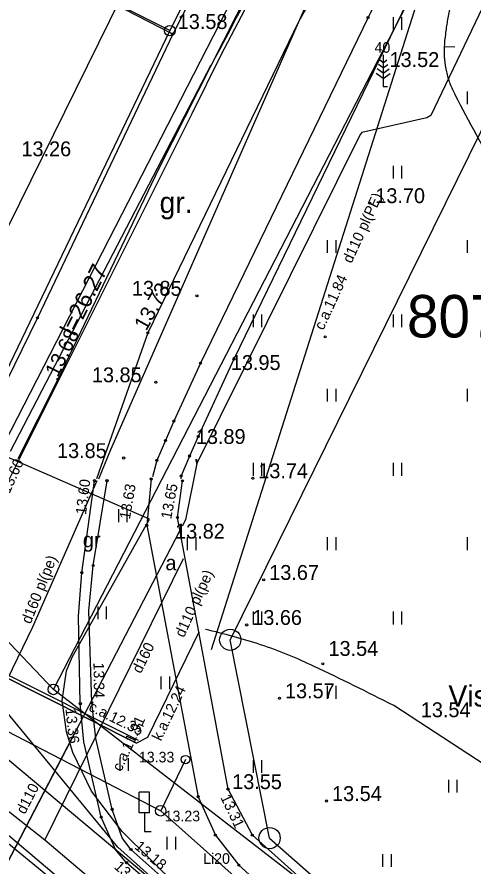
# Model space of a CAD drawing. Extents: x 503877 to 504025, y 304562 to 304725.
# Drawn here: x 503931.43 to 503952.92, y 304618.66 to 304658.69 of the extents above; entities that cross this region are included whole.
import ezdxf

# ---------------------------------------------------------------- set-up
doc = ezdxf.new("R2010")
doc.units = 0
for name, color, linetype in [('10', 7, 'Continuous'), ('13', 7, 'Continuous'), ('24', 7, 'Continuous'), ('25', 7, 'Continuous'), ('APGS_ACRL_####_####_#', 7, 'Continuous'), ('APGS_ELEM_####_####_#', 7, 'Continuous'), ('APGS_VADP_ZSPR_####_#', 7, 'Continuous'), ('APGS_VADP_ZSPR_TKST_#', 7, 'Continuous'), ('BUVE_EKAS_ADRS_TKST_#', 7, 'Continuous'), ('CELI_CMAL_####_####_#', 7, 'Continuous'), ('CELI_CSEG_####_TKST_#', 7, 'Continuous'), ('CELI_ELEM_####_####_#', 7, 'Continuous'), ('CELI_TAKA_####_####_#', 7, 'Continuous'), ('ELEK_ACRL_####_####_#', 7, 'Continuous'), ('ELEK_ELEM_####_####_#', 7, 'Continuous'), ('ELEK_STUT_####_####_#', 7, 'Continuous'), ('ELEK_VADP_VSPR_####_#', 7, 'Continuous'), ('ELEK_VADP_VSPR_TKST_#', 7, 'Continuous'), ('ELEK_VADV_ZSPR_####_#', 7, 'Continuous'), ('GAZE_VADP_VSP1_####_#', 7, 'Continuous'), ('GAZE_VADP_VSP2_####_#', 7, 'Continuous'), ('GAZE_VADP_ZSPD_TKST_#', 7, 'Continuous'), ('Level 37', 7, 'Continuous'), ('Level 46', 7, 'Continuous'), ('NORB_ZOGS_ZSTP_####_#', 7, 'Continuous'), ('RELJ_AATZ_####_TKST_#', 7, 'Continuous'), ('RELJ_ELEM_####_####_#', 7, 'Continuous'), ('RELJ_HORZ_KRIT_####_#', 7, 'Continuous'), ('RELJ_HORZ_PAMT_####_#', 7, 'Continuous'), ('SAKK_KKAN_####_####_#', 7, 'Continuous'), ('SAKK_KKAN_####_TKST_#', 7, 'Continuous'), ('SAKT_VADP_KABE_####_#', 7, 'Continuous'), ('SAKT_VADP_NEDR_####_#', 7, 'Continuous'), ('SKAN_VADP_PAST_####_I', 7, 'Continuous'), ('SKAN_VADP_SPDK_TKST_I', 7, 'Continuous'), ('TERT_DIAM_####_TKST_#', 7, 'Continuous'), ('TERT_ELEM_####_####_#', 7, 'Continuous'), ('UDTK_VADP_UDEN_####_#', 7, 'Continuous'), ('UDTK_VADP_UDEN_TKST_#', 7, 'Continuous')]:
    doc.layers.add(name, color=color, linetype=linetype)

msp = doc.modelspace()

# ---------------------------------------------------------------- linework, layer by layer
at = {"layer": '10'}
for centre in [(503938.631, 304658.048), (503933.144, 304627.024)]:
    msp.add_circle(centre, 0.25, dxfattribs=at)
at = {"layer": '13'}
msp.add_line((503926.838, 304633.583), (503933.144, 304627.024), dxfattribs=at)
at = {"layer": '24'}
for p, q in [((503951.131, 304682.848), (503938.631, 304658.048)), ((503938.631, 304658.048), (503897.583, 304678.92)), ((503933.144, 304627.024), (503952.592, 304664.678)), ((503938.631, 304658.048), (503926.838, 304633.583)), ((503960.823, 304605.633), (503933.144, 304627.024))]:
    msp.add_line(p, q, dxfattribs=at)
at = {"layer": '25'}
msp.add_line((503924.947, 304625.297), (503985.325, 304574.255), dxfattribs=at)
at = {"layer": 'APGS_ACRL_####_####_#'}
msp.add_line((503930.237, 304617.463), (503934.246, 304625.165), dxfattribs=at)
at = {"layer": 'APGS_ELEM_####_####_#'}
for p, q in [((503939.903, 304637.829), (503939.84, 304637.828)), ((503939.853, 304637.828), (503939.853, 304637.789)), ((503939.874, 304637.829), (503939.874, 304637.789)), ((503939.904, 304637.662), (503939.904, 304637.85))]:
    msp.add_line(p, q, dxfattribs=at)
msp.add_circle((503939.904, 304637.662), 0.00907, dxfattribs=at)
msp.add_ellipse((503939.864, 304637.789), major_axis=(0, 0.0151), ratio=0.695971, start_param=1.570796, end_param=4.712389, dxfattribs=at)
at = {"layer": 'APGS_VADP_ZSPR_####_#'}
msp.add_line((503939.108, 304634.506), (503930.237, 304617.463), dxfattribs=at)
for points in [[(503962.091, 304677.36), (503950.94, 304654.055), (503950.749, 304653.94), (503947.69, 304653.253), (503947.598, 304653.154), (503939.904, 304637.662)], [(503939.904, 304637.662), (503939.373, 304635.015), (503939.215, 304634.711)]]:
    msp.add_lwpolyline(points, dxfattribs=at)
at = {"layer": 'CELI_CMAL_####_####_#'}
for p, q in [((503937.753, 304636.934), (503937.542, 304634.751)), ((503934.483, 304632.519), (503935.08, 304636.853)), ((503938.994, 304635.119), (503939.23, 304636.849)), ((503941.374, 304622.324), (503938.994, 304635.119)), ((503937.542, 304634.751), (503939.968, 304621.969)), ((503934.319, 304630.471), (503934.483, 304632.519)), ((503934.411, 304626.352), (503934.319, 304630.471)), ((503934.578, 304624.555), (503934.411, 304626.352)), ((503935.397, 304621.008), (503934.578, 304624.555)), ((503942.522, 304620.157), (503941.374, 304622.324)), ((503939.968, 304621.969), (503940.779, 304620.16)), ((503936.063, 304619.479), (503935.397, 304621.008)), ((503940.779, 304620.16), (503941.882, 304618.748)), ((503950.55, 304613.018), (503942.522, 304620.157)), ((503936.593, 304618.863), (503936.063, 304619.479)), ((503946.502, 304610.359), (503936.593, 304618.863)), ((503941.882, 304618.748), (503948.456, 304612.839))]:
    msp.add_line(p, q, dxfattribs=at)
for points in [[(503964.434, 304683.858), (503952.135, 304666.661), (503951.57, 304665.843), (503951.057, 304664.963), (503950.617, 304664.103), (503947.974, 304658.67), (503940.075, 304642.39), (503938.82, 304639.661), (503938.43, 304638.742), (503938.02, 304637.811), (503937.81, 304637.042)], [(503960.285, 304675.777), (503953.257, 304665.972), (503952.709, 304665.141), (503952.2, 304664.263), (503951.73, 304663.364), (503949.548, 304658.848), (503941.655, 304642.576), (503939.971, 304638.935), (503939.558, 304638.014), (503939.163, 304637.077), (503939.144, 304636.942)]]:
    msp.add_lwpolyline(points, dxfattribs=at)
at = {"layer": 'CELI_ELEM_####_####_#'}
for p, q in [((503937.678, 304622.186), (503937.178, 304622.186)), ((503937.178, 304621.217), (503937.178, 304622.186)), ((503937.678, 304621.217), (503937.678, 304622.186)), ((503937.678, 304621.217), (503937.178, 304621.217)), ((503937.432, 304621.217), (503937.432, 304620.339)), ((503937.432, 304620.339), (503937.747, 304620.339))]:
    msp.add_line(p, q, dxfattribs=at)
at = {"layer": 'CELI_TAKA_####_####_#'}
for p, q in [((503935.016, 304632.859), (503935.67, 304636.852)), ((503934.812, 304630.718), (503935.016, 304632.859)), ((503934.952, 304626.401), (503934.812, 304630.718)), ((503935.148, 304624.712), (503934.952, 304626.401)), ((503935.915, 304621.375), (503935.148, 304624.712)), ((503936.38, 304620.026), (503935.915, 304621.375)), ((503936.798, 304619.482), (503936.38, 304620.026)), ((503946.769, 304610.685), (503936.798, 304619.482))]:
    msp.add_line(p, q, dxfattribs=at)
at = {"layer": 'ELEK_ACRL_####_####_#'}
for p, q in [((503923.292, 304631.393), (503937.063, 304624.493)), ((503937.153, 304624.623), (503923.308, 304631.521))]:
    msp.add_line(p, q, dxfattribs=at)
at = {"layer": 'ELEK_ELEM_####_####_#'}
for centre, radius in [((503939.367, 304623.718), 0.2), ((503938.2, 304621.309), 0.25)]:
    msp.add_circle(centre, radius, dxfattribs=at)
at = {"layer": 'ELEK_STUT_####_####_#'}
msp.add_line((503939.367, 304623.718), (503938.2, 304621.309), dxfattribs=at)
at = {"layer": 'ELEK_VADP_VSPR_####_#'}
for p, q in [((503937.063, 304624.493), (503923.292, 304631.393)), ((503939.998, 304629.719), (503937.58, 304624.758)), ((503937.58, 304624.758), (503937.063, 304624.493))]:
    msp.add_line(p, q, dxfattribs=at)
at = {"layer": 'ELEK_VADV_ZSPR_####_#'}
for p, q in [((503952.461, 304666.267), (503940.581, 304628.881)), ((503914.775, 304633.411), (503938.2, 304621.309)), ((503938.2, 304621.309), (503972.501, 304590.85))]:
    msp.add_line(p, q, dxfattribs=at)
at = {"layer": 'GAZE_VADP_VSP1_####_#'}
for p, q in [((503935.844, 304638.319), (503946.879, 304663.413)), ((503935.279, 304636.943), (503935.844, 304638.319))]:
    msp.add_line(p, q, dxfattribs=at)
at = {"layer": 'GAZE_VADP_VSP2_####_#'}
for p, q in [((503932.176, 304629.976), (503935.202, 304636.857)), ((503928.011, 304621.403), (503932.176, 304629.976))]:
    msp.add_line(p, q, dxfattribs=at)
at = {"layer": 'Level 37'}
for points in [[(503931.488, 304637.906), (503933.361, 304641.635), (503938.149, 304651.603), (503944.187, 304663.552), (503950.647, 304675.682), (503952.251, 304677.936)], [(503956.692, 304677.708), (503950.737, 304669.048), (503944.715, 304658.502), (503937.591, 304643.813), (503935.18, 304636.937)]]:
    msp.add_lwpolyline(points, dxfattribs=at)
at = {"layer": 'Level 46'}
for p, q in [((503926.16, 304638.991), (503960.977, 304709.6)), ((503980.064, 304707.607), (503941.479, 304629.359)), ((503943.333, 304620.019), (503941.479, 304629.359)), ((503943.333, 304620.019), (504006.701, 304564.361))]:
    msp.add_line(p, q, dxfattribs=at)
for centre in [(503941.479, 304629.359), (503943.333, 304620.019)]:
    msp.add_circle(centre, 0.5, dxfattribs=at)
at = {"layer": 'NORB_ZOGS_ZSTP_####_#'}
msp.add_line((503938.767, 304657.889), (503932.419, 304661.163), dxfattribs=at)
msp.add_lwpolyline([(503945.353, 304670.815), (503938.767, 304657.889), (503932.391, 304644.523), (503929.857, 304639.392)], dxfattribs=at)
at = {"layer": 'RELJ_ELEM_####_####_#'}
for centre in [(503947.974, 304658.67), (503938.767, 304657.889), (503948.058, 304649.926), (503939.908, 304645.563), (503932.391, 304644.522), (503937.591, 304643.813), (503945.957, 304643.63), (503941.655, 304642.576), (503940.075, 304642.39), (503933.361, 304641.635), (503937.972, 304641.489), (503938.82, 304639.661), (503939.971, 304638.935), (503938.43, 304638.742), (503936.454, 304637.92), (503938.02, 304637.811), (503939.558, 304638.014), (503935.08, 304636.853), (503935.67, 304636.852), (503937.753, 304636.934), (503939.163, 304637.077), (503939.23, 304636.849), (503942.541, 304636.967), (503938.994, 304635.119), (503937.542, 304634.751), (503935.016, 304632.859), (503934.483, 304632.519), (503943.058, 304632.181), (503942.256, 304630.06), (503945.845, 304628.228), (503943.8, 304626.606), (503934.411, 304626.352), (503934.952, 304626.401), (503941.374, 304622.324), (503939.968, 304621.969), (503946.019, 304621.767), (503935.915, 304621.375), (503935.397, 304621.008), (503940.779, 304620.16), (503942.522, 304620.157), (503936.798, 304619.482), (503936.593, 304618.863), (503941.882, 304618.748)]:
    msp.add_circle(centre, 0.05, dxfattribs=at)
at = {"layer": 'RELJ_HORZ_KRIT_####_#'}
msp.add_line((503951.564, 304657.296), (503952.064, 304657.28), dxfattribs=at)
at = {"layer": 'RELJ_HORZ_PAMT_####_#'}
for p, q in [((503930.834, 304638.618), (503946.923, 304669.929)), ((503966.227, 304615.164), (503949.188, 304626.264))]:
    msp.add_line(p, q, dxfattribs=at)
for points in [[(503952.816, 304672.072), (503952.987, 304664.738), (503952.905, 304663.502), (503952.654, 304662.245), (503952.49, 304661.612), (503952.312, 304660.984), (503952.133, 304660.355), (503951.965, 304659.719), (503951.712, 304658.5), (503951.624, 304657.887), (503951.562, 304657.273), (503951.573, 304656.693), (503951.668, 304656.113), (503951.833, 304655.556), (503952.085, 304655.015), (503956.212, 304647.7)], [(503949.188, 304626.264), (503945.432, 304628.106), (503944.194, 304628.656), (503942.913, 304629.125), (503941.61, 304629.519), (503940.305, 304629.848)]]:
    msp.add_spline(points, degree=3, dxfattribs=at)
at = {"layer": 'SAKK_KKAN_####_####_#'}
for p, q in [((503929.303, 304633.417), (503931.538, 304637.883)), ((503936.176, 304619.589), (503925.437, 304632.6)), ((503945.607, 304611.208), (503936.176, 304619.589))]:
    msp.add_line(p, q, dxfattribs=at)
for points in [[(503939.678, 304654.149), (503941.056, 304656.903), (503947.777, 304669.708), (503952.362, 304677.93)], [(503931.538, 304637.883), (503939.678, 304654.149)]]:
    msp.add_lwpolyline(points, dxfattribs=at)
at = {"layer": 'SAKT_VADP_KABE_####_#'}
for p, q in [((503937.674, 304635.041), (503930.975, 304637.966)), ((503934.034, 304628.544), (503937.674, 304635.041)), ((503933.754, 304627.901), (503934.034, 304628.544)), ((503933.557, 304626.502), (503933.754, 304627.901)), ((503933.757, 304625.029), (503933.557, 304626.502)), ((503934.062, 304624.051), (503933.757, 304625.029)), ((503934.945, 304622.232), (503934.062, 304624.051)), ((503936.38, 304620.327), (503934.945, 304622.232)), ((503940.354, 304616.433), (503936.38, 304620.327))]:
    msp.add_line(p, q, dxfattribs=at)
msp.add_lwpolyline([(503931.122, 304638.249), (503940.575, 304656.435)], dxfattribs=at)
msp.add_spline([(503940.594, 304656.424), (503946.756, 304668.251), (503948.98, 304672.652), (503951.815, 304677.958)], degree=3, dxfattribs=at)
at = {"layer": 'SAKT_VADP_NEDR_####_#'}
msp.add_line((503997.217, 304568.475), (503924.507, 304629.123), dxfattribs=at)
at = {"layer": 'SKAN_VADP_PAST_####_I'}
msp.add_line((503945.224, 304608.195), (503926.692, 304623.27), dxfattribs=at)
at = {"layer": 'TERT_ELEM_####_####_#'}
for p, q in [((503949.171, 304658.087), (503949.171, 304658.687)), ((503949.571, 304658.087), (503949.571, 304658.687)), ((503948.69, 304656.916), (503948.69, 304655.416)), ((503948.69, 304656.54), (503948.514, 304656.668)), ((503948.69, 304656.54), (503948.864, 304656.668)), ((503948.69, 304656.04), (503948.412, 304656.244)), ((503948.69, 304656.29), (503948.474, 304656.448)), ((503948.69, 304656.29), (503948.906, 304656.448)), ((503948.69, 304656.04), (503948.968, 304656.244)), ((503948.69, 304655.79), (503948.358, 304656.034)), ((503948.69, 304655.79), (503949.024, 304656.034)), ((503948.69, 304655.416), (503948.89, 304655.416)), ((503952.671, 304654.587), (503952.671, 304655.187)), ((503949.171, 304651.087), (503949.171, 304651.687)), ((503949.571, 304651.087), (503949.571, 304651.687)), ((503946.071, 304647.587), (503946.071, 304648.187)), ((503946.471, 304647.587), (503946.471, 304648.187)), ((503952.671, 304647.587), (503952.671, 304648.187)), ((503942.571, 304644.087), (503942.571, 304644.687)), ((503942.971, 304644.087), (503942.971, 304644.687)), ((503949.171, 304644.087), (503949.171, 304644.687)), ((503949.571, 304644.087), (503949.571, 304644.687)), ((503946.071, 304640.587), (503946.071, 304641.187)), ((503946.471, 304640.587), (503946.471, 304641.187)), ((503952.671, 304640.587), (503952.671, 304641.187)), ((503942.571, 304637.087), (503942.571, 304637.687)), ((503942.971, 304637.087), (503942.971, 304637.687)), ((503949.171, 304637.087), (503949.171, 304637.687)), ((503949.571, 304637.087), (503949.571, 304637.687)), ((503936.222, 304634.907), (503936.222, 304635.507)), ((503936.622, 304634.907), (503936.622, 304635.507)), ((503939.471, 304633.587), (503939.471, 304634.187)), ((503939.871, 304633.587), (503939.871, 304634.187)), ((503946.071, 304633.587), (503946.071, 304634.187)), ((503946.471, 304633.587), (503946.471, 304634.187)), ((503952.671, 304633.587), (503952.671, 304634.187)), ((503935.247, 304630.335), (503935.247, 304630.935)), ((503935.647, 304630.335), (503935.647, 304630.935)), ((503942.571, 304630.087), (503942.571, 304630.687)), ((503942.971, 304630.087), (503942.971, 304630.687)), ((503949.171, 304630.087), (503949.171, 304630.687)), ((503949.571, 304630.087), (503949.571, 304630.687)), ((503938.23, 304627.035), (503938.23, 304627.635)), ((503938.63, 304627.035), (503938.63, 304627.635)), ((503946.071, 304626.587), (503946.071, 304627.187)), ((503946.471, 304626.587), (503946.471, 304627.187)), ((503936.286, 304623.182), (503936.286, 304623.782)), ((503936.686, 304623.182), (503936.686, 304623.782)), ((503942.571, 304623.087), (503942.571, 304623.687)), ((503942.971, 304623.087), (503942.971, 304623.687)), ((503951.779, 304622.162), (503951.779, 304622.762)), ((503952.179, 304622.162), (503952.179, 304622.762)), ((503938.507, 304619.479), (503938.507, 304620.079)), ((503938.907, 304619.479), (503938.907, 304620.079)), ((503948.679, 304618.662), (503948.679, 304619.262)), ((503949.079, 304618.662), (503949.079, 304619.262))]:
    msp.add_line(p, q, dxfattribs=at)
at = {"layer": 'UDTK_VADP_UDEN_####_#'}
for p, q in [((503932.733, 304619.928), (503939.281, 304633.189)), ((503932.733, 304619.928), (503928.931, 304622.91)), ((503941.933, 304612.16), (503932.733, 304619.928))]:
    msp.add_line(p, q, dxfattribs=at)

# ---------------------------------------------------------------- texts
at = {"layer": '24'}
msp.add_text('80760080061', height=2, dxfattribs=at).set_placement((503949.809, 304643.599))
at = {"layer": 'APGS_VADP_ZSPR_TKST_#'}
msp.add_text('d110', height=0.5, rotation=62.5031, dxfattribs=at).set_placement((503931.797, 304621.109))
at = {"layer": 'BUVE_EKAS_ADRS_TKST_#'}
msp.add_text('Viskalnu iela 10', height=1, dxfattribs=at).set_placement((503951.763, 304626.215))
at = {"layer": 'CELI_CSEG_####_TKST_#'}
for s, p in [('gr', (503934.531, 304633.717)), ('a', (503938.423, 304632.635))]:
    msp.add_text(s, height=0.7, dxfattribs=at).set_placement(p)
at = {"layer": 'ELEK_VADP_VSPR_TKST_#'}
for s, rotation, p in [('k.a.12.24', 64.3683, (503938.213, 304624.562)), ('c.a.12.35', 333.8159, (503934.764, 304626.044))]:
    msp.add_text(s, height=0.5, rotation=rotation, dxfattribs=at).set_placement(p)
at = {"layer": 'GAZE_VADP_ZSPD_TKST_#'}
msp.add_text('d160 pl(pe)', height=0.5, rotation=68.1966, dxfattribs=at).set_placement((503932.067, 304630.073))
at = {"layer": 'Level 37'}
msp.add_text(' gr.', height=1, dxfattribs=at).set_placement((503937.777, 304649.456))
at = {"layer": 'RELJ_AATZ_####_TKST_#'}
for s, height, p in [('13.58', 0.7, (503939.004, 304658.126)), ('13.52', 0.7, (503948.989, 304656.336)), ('13.26', 0.7, (503931.636, 304652.133)), (' 13.70', 0.7, (503948.058, 304649.926)), (' 13.85', 0.7, (503936.584, 304645.563)), (' 13.95', 0.7, (503941.249, 304642.067)), (' 13.85', 0.7, (503934.699, 304641.489)), (' 13.89', 0.7, (503939.599, 304638.583)), (' 13.85', 0.7, (503933.054, 304637.92)), (' 13.74', 0.7, (503942.541, 304636.967)), (' 13.82', 0.7, (503938.619, 304634.126)), (' 13.67', 0.7, (503943.058, 304632.181)), (' 13.66', 0.7, (503942.256, 304630.06)), ('13.54', 0.7, (503946.111, 304628.602)), (' 13.57', 0.7, (503943.8, 304626.606)), ('13.54', 0.7, (503950.462, 304625.714)), (' 13.33', 0.5, (503936.985, 304623.584)), (' 13.55', 0.7, (503941.311, 304622.328)), (' 13.54', 0.7, (503946.019, 304621.767)), (' 13.23', 0.5, (503938.2, 304620.809))]:
    msp.add_text(s, height=height, dxfattribs=at).set_placement(p)
for s, height, rotation, p in [('13.73', 0.7, 60.6451, (503937.517, 304643.872)), ('13.68', 0.7, 63.5135, (503933.341, 304641.689)), (' 13.60', 0.5, 65.8065, (503930.995, 304636.044)), (' 13.60', 0.5, 82.7583, (503934.656, 304635.05)), (' 13.63', 0.5, 80.3238, (503936.715, 304634.823)), (' 13.65', 0.5, 79.2253, (503938.659, 304634.834)), (' 13.34', 0.5, 270.8772, (503935.027, 304628.471)), (' 13.36', 0.5, 275.8115, (503933.689, 304626.301)), (' 13.31', 0.5, 295.4747, (503940.923, 304622.109)), (' 13.18', 0.5, 320.1951, (503936.79, 304619.675)), (' 13.19', 0.5, 316.8008, (503935.832, 304618.76))]:
    msp.add_text(s, height=height, rotation=rotation, dxfattribs=at).set_placement(p)
at = {"layer": 'SAKK_KKAN_####_TKST_#'}
msp.add_text('l=26.27', height=0.8, rotation=63.4154, dxfattribs=at).set_placement((503934.138, 304643.621))
at = {"layer": 'SKAN_VADP_SPDK_TKST_I'}
for s, p in [('d110 pl(PE)', (503947.197, 304647.058)), ('c.a.11.84', (503945.868, 304643.91)), ('d110 pl(pe)', (503939.292, 304629.435)), ('c.a.11.91', (503936.339, 304623.124))]:
    msp.add_text(s, height=0.5, rotation=65.3954, dxfattribs=at).set_placement(p)
at = {"layer": 'TERT_DIAM_####_TKST_#'}
for s, p in [('40', (503948.281, 304657.008)), ('Li20', (503940.202, 304618.807))]:
    msp.add_text(s, height=0.5, dxfattribs=at).set_placement(p)
at = {"layer": 'UDTK_VADP_UDEN_TKST_#'}
msp.add_text('d160', height=0.5, rotation=63.721, dxfattribs=at).set_placement((503937.265, 304627.74))

doc.saveas('drawing.dxf')
